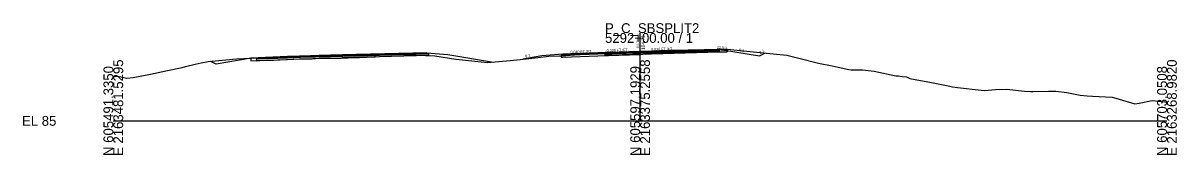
# Model space of a CAD drawing. Extents: x -26 to 1303, y -10 to 12033.
# Drawn here: x -25.7 to 302.8, y 6490.3 to 6527.8 of the extents above; entities that cross this region are included whole.
import ezdxf

# ---------------------------------------------------------------- set-up
doc = ezdxf.new("R2010")
doc.units = 0
for name, color, linetype in [('RD_GPK_XS_Cell', 7, 'Continuous'), ('RD_XS_Base', 7, 'Continuous'), ('RD_XS_ExGround', 7, 'Continuous'), ('RD_XS_ExPaveRet', 7, 'Continuous'), ('RD_XS_Greenside', 7, 'Continuous'), ('RD_XS_Pave', 7, 'Continuous'), ('RD_XS_PaveOvlay_CP', 7, 'Continuous'), ('RD_XS_TieSlope', 7, 'Continuous'), ('RD_XS_TX_Elev_EX', 7, 'Continuous'), ('RD_XS_TX_Elev_PR', 7, 'Continuous'), ('RD_XS_TX_ShdSlope', 7, 'Continuous'), ('RD_XS_TX_Slope', 7, 'Continuous')]:
    doc.layers.add(name, color=color, linetype=linetype)

msp = doc.modelspace()

# ---------------------------------------------------------------- linework, layer by layer
at = {"layer": 'RD_GPK_XS_Cell'}
for p, q in [((150, 6500), (150, 6525)), ((0, 6500), (150, 6500)), ((150, 6500), (300, 6500))]:
    msp.add_line(p, q, dxfattribs=at)
at = {"layer": 'RD_XS_Base'}
for p, q in [((53.25, 6518.14), (49.6, 6517.99)), ((61.8, 6518.36), (53.25, 6518.14)), ((65.25, 6518.45), (61.8, 6518.36)), ((65.25, 6518.45), (89.75, 6519.09)), ((65.25, 6517.95), (65.25, 6518.61)), ((65.25, 6518.61), (65.25, 6518.61)), ((65.25, 6518.61), (65.25, 6518.61)), ((65.25, 6518.61), (65.25, 6518.45)), ((89.75, 6518.59), (65.25, 6517.95)), ((65.25, 6518.45), (65.25, 6518.45)), ((65.25, 6517.95), (65.25, 6518.45)), ((65.25, 6518.45), (65.25, 6518.45)), ((65.25, 6518.45), (65.25, 6518.45)), ((89.25, 6519.08), (89.25, 6519.08)), ((89.25, 6519.08), (89.25, 6519.08)), ((89.25, 6519.08), (89.25, 6519.08)), ((89.25, 6518.58), (89.25, 6518.58)), ((89.25, 6518.58), (89.25, 6518.58)), ((89.75, 6519.09), (89.75, 6518.59)), ((89.75, 6519.06), (89.75, 6519.06)), ((128, 6518.66), (127.5, 6518.64)), ((127.5, 6518.64), (127.5, 6518.64)), ((127.5, 6518.64), (127.5, 6518.14)), ((127.5, 6518.14), (128, 6518.16)), ((138, 6519.06), (128, 6518.66)), ((128, 6518.66), (128, 6518.66)), ((128, 6518.16), (138, 6518.56)), ((128, 6518.16), (128, 6518.16)), ((136, 6518.98), (136, 6518.98)), ((136, 6518.48), (136, 6518.48)), ((150, 6519.39), (138, 6519.06)), ((138, 6518.56), (150, 6518.89)), ((150, 6519.39), (172, 6520.01)), ((150, 6518.89), (150, 6519.55)), ((150, 6519.55), (150, 6519.55)), ((150, 6519.55), (150, 6519.55)), ((150, 6519.55), (150, 6519.39)), ((172.5, 6519.52), (150, 6518.89)), ((150, 6519.39), (150, 6519.39)), ((150, 6518.89), (150, 6519.39)), ((150, 6519.39), (150, 6519.39)), ((150, 6519.39), (150, 6519.39)), ((150, 6518.89), (150, 6518.89)), ((162, 6519.73), (162, 6519.73)), ((162, 6519.73), (162, 6519.73)), ((162, 6519.23), (162, 6519.23)), ((162, 6519.23), (162, 6519.23)), ((172, 6520.01), (172, 6520.01)), ((172.5, 6520.02), (172.5, 6519.52)), ((172.5, 6519.99), (172.5, 6519.99)), ((41.09, 6517.65), (40.75, 6517.64)), ((40.75, 6517.64), (40.75, 6517.48)), ((40.75, 6517.48), (40.75, 6517.14)), ((40.75, 6517.14), (41.09, 6517.15)), ((41.25, 6517.66), (41.09, 6517.65)), ((41.09, 6517.15), (41.25, 6517.16)), ((49.6, 6517.99), (41.25, 6517.66)), ((41.25, 6517.16), (49.6, 6517.49)), ((49.6, 6517.49), (53.25, 6517.64)), ((53.25, 6517.64), (61.8, 6517.86)), ((61.8, 6517.86), (65.25, 6517.95)), ((65.25, 6517.95), (65.25, 6517.95))]:
    msp.add_line(p, q, dxfattribs=at)
at = {"layer": 'RD_XS_ExGround'}
msp.add_lwpolyline([(0, 6512.77), (0.83, 6512.74), (1.62, 6512.62), (3.85, 6512.15), (5.64, 6512.38), (10.6, 6513.33), (15.4, 6514.38), (19.65, 6515.24), (20.54, 6515.5), (23.28, 6516.15), (25, 6516.51), (27.01, 6516.87), (35.08, 6517.66), (39.15, 6517.84), (45.65, 6518.06), (53.25, 6518.43), (56.63, 6518.46), (57.15, 6518.5), (57.35, 6518.5), (57.47, 6518.51), (58.7, 6518.6), (60.31, 6518.57), (64.64, 6518.63), (68.92, 6518.78), (74.55, 6518.97), (83.33, 6518.81), (84.25, 6518.79), (85.1, 6518.75), (86.25, 6518.72), (91.54, 6518.5), (97.51, 6517.59), (97.53, 6517.58), (97.58, 6517.58), (102.97, 6516.98), (106.57, 6516.58), (113.03, 6517.21), (115.85, 6517.51), (120.88, 6518.08), (123.99, 6518.43), (127.08, 6518.5), (127.18, 6518.5), (127.39, 6518.5), (128.81, 6518.61), (138.58, 6519.35), (140.06, 6519.46), (141.98, 6519.5), (150.74, 6519.72), (152.7, 6519.79), (155.8, 6519.96), (158.1, 6520.08), (169.26, 6520.27), (174.76, 6520.39), (187.87, 6519.13), (191.78, 6518.75), (195.61, 6517.73), (200.81, 6516.41), (204.66, 6515.66), (206.4, 6515.3), (209.46, 6514.64), (210.13, 6514.51), (212.74, 6514.5), (213.3, 6514.5), (216.61, 6514.13), (222.8, 6512.87), (223.54, 6512.78), (224.6, 6512.64), (225.82, 6512.52), (226.79, 6512.06), (229.8, 6511.48), (232.5, 6511.05), (238.22, 6509.84), (238.94, 6509.65), (240.34, 6509.5), (247.07, 6508.75), (248.01, 6508.69), (251.2, 6508.96), (254.45, 6509.02), (259.45, 6508.48), (261.15, 6508.4), (261.78, 6508.32), (266.31, 6508.46), (267.77, 6508.49), (268.33, 6508.44), (271.5, 6508.09), (275.25, 6507.34), (277.24, 6507.1), (278.81, 6507.04), (284.39, 6506.73), (285.44, 6506.46), (290.88, 6504.86), (292.11, 6505.05), (295.8, 6505.78), (299.37, 6505.38), (300, 6505.31)], dxfattribs=at)
at = {"layer": 'RD_XS_ExPaveRet'}
for points in [[(70.09, 6518.82), (68.92, 6518.78), (64.91, 6518.64), (64.64, 6518.63), (63.74, 6518.61), (60.31, 6518.57), (58.86, 6518.59), (58.7, 6518.6), (58.58, 6518.59), (57.47, 6518.51), (57.41, 6518.5), (57.35, 6518.5), (57.24, 6518.5), (56.97, 6518.48), (56.87, 6518.48), (56.63, 6518.46), (53.37, 6518.43), (53.25, 6518.43), (52.99, 6518.42), (45.65, 6518.06), (44.39, 6518.02), (39.15, 6517.84), (39.15, 6517.84), (39.15, 6517.16), (39.15, 6517.09), (39.15, 6517.09), (44.39, 6517.27), (45.65, 6517.31), (52.99, 6517.67), (53.25, 6517.68), (53.37, 6517.68), (56.63, 6517.71), (56.87, 6517.73), (56.97, 6517.73), (57.24, 6517.75), (57.35, 6517.75), (57.41, 6517.75), (57.47, 6517.76), (58.58, 6517.84), (58.7, 6517.85), (58.86, 6517.84), (60.31, 6517.82), (63.74, 6517.86), (64.64, 6517.88), (64.91, 6517.89), (68.92, 6518.03), (70.09, 6518.07), (74.55, 6518.22), (74.55, 6518.36), (74.55, 6518.97), (70.09, 6518.82)], [(70.09, 6518.82), (68.92, 6518.78), (64.91, 6518.64), (64.64, 6518.63), (63.74, 6518.61), (60.31, 6518.57), (58.86, 6518.59), (58.7, 6518.6), (58.58, 6518.59), (57.47, 6518.51), (57.41, 6518.5), (57.35, 6518.5), (57.24, 6518.5), (56.97, 6518.48), (56.87, 6518.48), (56.63, 6518.46), (53.37, 6518.43), (53.25, 6518.43), (52.99, 6518.42), (45.65, 6518.06), (44.39, 6518.02), (39.15, 6517.84), (39.15, 6517.16), (39.15, 6517.09), (44.39, 6517.27), (45.65, 6517.31), (52.99, 6517.67), (53.25, 6517.68), (53.37, 6517.68), (56.63, 6517.71), (56.87, 6517.73), (56.97, 6517.73), (57.24, 6517.75), (57.35, 6517.75), (57.41, 6517.75), (57.47, 6517.76), (58.58, 6517.84), (58.7, 6517.85), (58.86, 6517.84), (60.31, 6517.82), (63.74, 6517.86), (64.64, 6517.88), (64.91, 6517.89), (68.92, 6518.03), (70.09, 6518.07), (74.55, 6518.22), (74.55, 6518.36), (74.55, 6518.97), (70.09, 6518.82)], [(174.76, 6520.39), (174.76, 6520.39), (174.76, 6520.39), (174.76, 6519.64), (174.76, 6519.64), (169.26, 6519.52), (169.26, 6519.52), (158.1, 6519.33), (158.1, 6519.33), (155.8, 6519.21), (152.7, 6519.04), (152.7, 6519.04), (150.74, 6518.97), (150.74, 6518.97), (150.74, 6518.97), (141.98, 6518.75), (141.98, 6518.75), (140.06, 6518.71), (140.06, 6518.71), (140.06, 6519.46), (140.06, 6519.46), (140.06, 6519.46), (141.98, 6519.5), (141.98, 6519.5), (150.74, 6519.72), (150.74, 6519.72), (150.74, 6519.72), (152.7, 6519.79), (152.7, 6519.79), (155.8, 6519.96), (158.1, 6520.08), (158.1, 6520.08), (169.26, 6520.27), (169.26, 6520.27), (174.76, 6520.39)], [(169.26, 6520.27), (158.1, 6520.08), (155.8, 6519.96), (152.7, 6519.79), (150.74, 6519.72), (141.98, 6519.5), (140.06, 6519.46), (140.06, 6519.46), (140.06, 6518.71), (140.06, 6518.71), (141.98, 6518.75), (150.74, 6518.97), (152.7, 6519.04), (155.8, 6519.21), (158.1, 6519.33), (169.26, 6519.52), (174.76, 6519.64), (174.76, 6520.39), (169.26, 6520.27)]]:
    msp.add_lwpolyline(points, dxfattribs=at)
at = {"layer": 'RD_XS_Greenside'}
for p, q in [((95.25, 6518.91), (108.27, 6516.74)), ((122, 6518.5), (116.61, 6517.6)), ((174, 6520.17), (184, 6518.5)), ((184, 6518.5), (185.67, 6519.34)), ((29.24, 6516.15), (27.76, 6516.9)), ((39.25, 6517.82), (29.24, 6516.15))]:
    msp.add_line(p, q, dxfattribs=at)
at = {"layer": 'RD_XS_Pave'}
for p, q in [((49.6, 6518.31), (41.25, 6517.98)), ((41.25, 6517.82), (49.6, 6518.15)), ((49.6, 6518.15), (41.25, 6517.82)), ((53.25, 6518.46), (49.6, 6518.31)), ((49.6, 6518.15), (53.25, 6518.3)), ((53.25, 6518.3), (49.6, 6518.15)), ((49.6, 6517.99), (53.25, 6518.14)), ((61.8, 6518.68), (53.25, 6518.46)), ((53.25, 6518.3), (61.8, 6518.52)), ((61.8, 6518.52), (53.25, 6518.3)), ((53.25, 6518.14), (61.8, 6518.36)), ((65.25, 6518.77), (61.8, 6518.68)), ((61.8, 6518.52), (65.25, 6518.61)), ((65.25, 6518.61), (61.8, 6518.52)), ((61.8, 6518.36), (65.25, 6518.45)), ((89.25, 6519.39), (65.25, 6518.77)), ((89.25, 6519.23), (65.25, 6518.61)), ((65.25, 6518.61), (89.25, 6519.23)), ((65.25, 6518.45), (89.25, 6519.08)), ((65.25, 6518.77), (65.25, 6518.77)), ((65.25, 6518.61), (65.25, 6518.61)), ((65.25, 6518.61), (65.25, 6518.61)), ((65.25, 6518.61), (65.25, 6518.45)), ((65.25, 6518.61), (65.25, 6518.61)), ((65.25, 6518.45), (65.25, 6518.61)), ((65.25, 6518.61), (65.25, 6518.61)), ((65.25, 6518.61), (65.25, 6518.61)), ((65.25, 6518.45), (65.25, 6518.45)), ((65.25, 6518.45), (65.25, 6518.45)), ((89.25, 6519.23), (89.25, 6519.39)), ((89.25, 6519.39), (89.25, 6519.39)), ((89.25, 6519.39), (89.25, 6519.39)), ((89.25, 6519.39), (89.25, 6519.39)), ((89.25, 6519.08), (89.25, 6519.23)), ((89.25, 6519.23), (89.25, 6519.23)), ((89.25, 6519.23), (89.25, 6519.23)), ((89.25, 6519.23), (89.25, 6519.23)), ((89.25, 6519.23), (89.25, 6519.23)), ((89.25, 6519.23), (89.25, 6519.23)), ((89.25, 6519.08), (89.25, 6519.08)), ((89.25, 6519.08), (89.25, 6519.08)), ((138, 6519.38), (128, 6518.98)), ((128, 6518.82), (138, 6519.22)), ((138, 6519.22), (128, 6518.82)), ((128, 6518.66), (138, 6519.06)), ((128, 6518.98), (128, 6518.98)), ((128, 6518.98), (128, 6518.82)), ((128, 6518.82), (128, 6518.82)), ((128, 6518.82), (128, 6518.66)), ((136, 6519.3), (136, 6519.3)), ((136, 6519.14), (136, 6519.14)), ((136, 6519.14), (136, 6519.14)), ((136, 6518.98), (136, 6518.98)), ((150, 6519.71), (138, 6519.38)), ((138, 6519.22), (150, 6519.55)), ((150, 6519.55), (138, 6519.22)), ((138, 6519.06), (150, 6519.39)), ((172, 6520.33), (150, 6519.71)), ((172, 6520.17), (150, 6519.55)), ((150, 6519.55), (172, 6520.17)), ((150, 6519.39), (172.5, 6520.02)), ((150, 6519.71), (150, 6519.71)), ((150, 6519.55), (150, 6519.55)), ((150, 6519.55), (150, 6519.55)), ((150, 6519.55), (150, 6519.39)), ((150, 6519.55), (150, 6519.55)), ((150, 6519.39), (150, 6519.55)), ((150, 6519.55), (150, 6519.55)), ((150, 6519.55), (150, 6519.55)), ((150, 6519.39), (150, 6519.39)), ((150, 6519.39), (150, 6519.39)), ((162, 6520.05), (162, 6520.05)), ((162, 6520.05), (162, 6520.05)), ((162, 6519.89), (162, 6519.89)), ((162, 6519.89), (162, 6519.89)), ((162, 6519.89), (162, 6519.89)), ((162, 6519.89), (162, 6519.89)), ((162, 6519.73), (162, 6519.73)), ((162, 6519.73), (162, 6519.73)), ((172, 6520.17), (172, 6520.33)), ((172, 6520.33), (172, 6520.33)), ((172, 6520.01), (172, 6520.17)), ((172, 6520.17), (172, 6520.17)), ((41.25, 6517.66), (49.6, 6517.99)), ((41.25, 6517.98), (41.25, 6517.93)), ((41.25, 6517.93), (41.25, 6517.82)), ((41.25, 6517.82), (41.25, 6517.77)), ((41.25, 6517.77), (41.25, 6517.66))]:
    msp.add_line(p, q, dxfattribs=at)
at = {"layer": 'RD_XS_PaveOvlay_CP'}
for p, q in [((49.6, 6518.31), (41.25, 6517.98)), ((53.25, 6518.46), (49.6, 6518.31)), ((61.8, 6518.68), (53.25, 6518.46)), ((65.25, 6518.77), (61.8, 6518.68)), ((89.25, 6519.39), (65.25, 6518.77)), ((65.25, 6518.77), (65.25, 6518.77)), ((89.25, 6519.39), (89.25, 6519.39)), ((89.25, 6519.39), (89.25, 6519.39)), ((138, 6519.38), (128, 6518.98)), ((136, 6519.3), (136, 6519.3)), ((150, 6519.71), (138, 6519.38)), ((172, 6520.33), (150, 6519.71)), ((150, 6519.71), (150, 6519.71)), ((162, 6520.05), (162, 6520.05)), ((162, 6520.05), (162, 6520.05))]:
    msp.add_line(p, q, dxfattribs=at)
at = {"layer": 'RD_XS_TieSlope'}
for p, q in [((89.25, 6519.39), (95.25, 6518.91)), ((128, 6518.98), (122, 6518.5)), ((172, 6520.33), (174, 6520.17)), ((41.25, 6517.98), (39.25, 6517.82))]:
    msp.add_line(p, q, dxfattribs=at)

# ---------------------------------------------------------------- texts
at = {"layer": 'RD_GPK_XS_Cell'}
for s, p in [('5292+00.00 / 1', (140, 6522.2)), ('P_C_SBSPLIT2', (140, 6525)), ('EL 85', (-26, 6498.6))]:
    msp.add_text(s, height=2.8, dxfattribs=at).set_placement(p)
for s, p in [('N 605491.3350', (0, 6490)), ('E 2163481.5295', (2.8, 6490)), ('N 605597.1929', (150, 6490)), ('E 2163375.2558', (152.8, 6490)), ('N 605703.0508', (300, 6490)), ('E 2163268.9820', (302.8, 6490))]:
    msp.add_text(s, height=2.8, rotation=90, dxfattribs=at).set_placement(p)
at = {"layer": 'RD_XS_TX_Elev_EX'}
msp.add_text('104.70', height=0.6, rotation=90, dxfattribs=at).set_placement((149.6, 6520.65))
at = {"layer": 'RD_XS_TX_Elev_PR'}
msp.add_text('104.71', height=1, rotation=90, dxfattribs=at).set_placement((151.36, 6520.15))
at = {"layer": 'RD_XS_TX_ShdSlope'}
msp.add_text('12.5:1', height=0.75, rotation=355.4261, dxfattribs=at).set_placement((171.84, 6520.61))
at = {"layer": 'RD_XS_TX_Slope'}
for s, rotation, p in [('6:1', 9.4642, (117.34, 6518.06)), ('0.040 FT./FT.', 2.2906, (130.15, 6519.19)), ('0.030 FT./FT.', 1.7184, (140.48, 6519.66)), ('0.030 FT./FT.', 1.7184, (153.16, 6519.98)), ('6:1', 350.5358, (178.13, 6519.86)), ('2:1', 26.5651, (184.2, 6519.02))]:
    msp.add_text(s, height=0.75, rotation=rotation, dxfattribs=at).set_placement(p)

doc.saveas('drawing.dxf')
